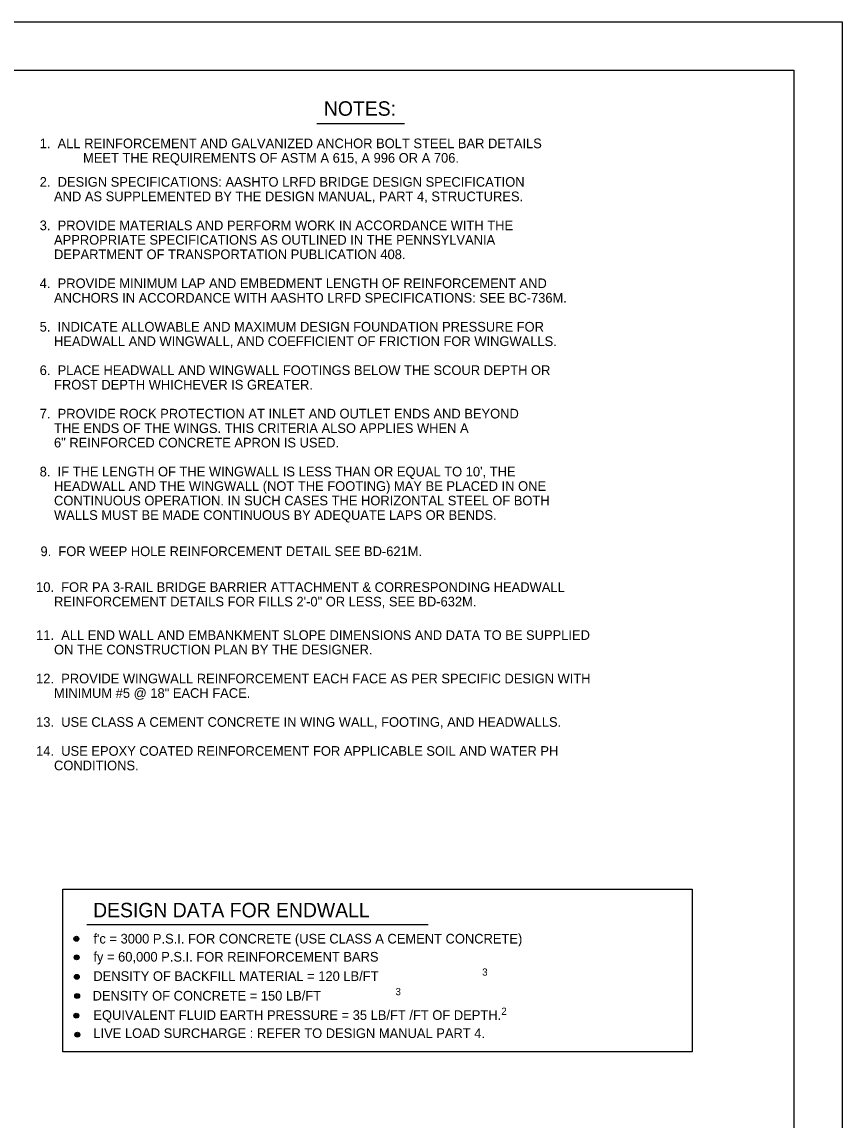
# Model space of a CAD drawing. Extents: x 639011 to 639866, y 298840 to 300028.
# Drawn here: x 639597.4 to 639852.3, y 299686.7 to 300027.8 of the extents above; entities that cross this region are included whole.
import ezdxf

# ---------------------------------------------------------------- set-up
doc = ezdxf.new("R2010")
doc.units = 0
doc.layers.add('2', color=7, linetype='Continuous')
doc.layers.add('PLT-BNDY', color=7, linetype='Continuous')

msp = doc.modelspace()

# ---------------------------------------------------------------- linework, layer by layer
at = {"layer": '2'}
for p, q in [((639051.26, 300012.83), (639837.26, 300012.83)), ((639837.26, 300012.83), (639837.26, 299448.83)), ((639689.02, 299996.32), (639716.27, 299996.32)), ((639617.6, 299747.4), (639723.63, 299747.4))]:
    msp.add_line(p, q, dxfattribs=at)
msp.add_lwpolyline([(639610.08, 299758.44), (639805.72, 299758.44), (639805.72, 299707.89), (639610.08, 299707.89)], close=True, dxfattribs=at)
for centre, radius in [((639614.32, 299743), 0.763), ((639614.32, 299743), 0.763), ((639614.32, 299743), 0.545), ((639614.32, 299743), 0.545), ((639614.32, 299743), 0.298), ((639614.32, 299743), 0.298), ((639614.32, 299743), 0.15), ((639614.32, 299743), 0.15), ((639614.32, 299743), 0.0644), ((639614.32, 299743), 0.0644), ((639614.4, 299737.23), 0.763), ((639614.4, 299737.23), 0.763), ((639614.4, 299737.23), 0.545), ((639614.4, 299737.23), 0.545), ((639614.4, 299737.23), 0.298), ((639614.4, 299737.23), 0.298), ((639614.4, 299737.23), 0.15), ((639614.4, 299737.23), 0.15), ((639614.4, 299737.23), 0.0644), ((639614.4, 299737.23), 0.0644), ((639614.46, 299731.16), 0.763), ((639614.46, 299731.16), 0.763), ((639614.46, 299731.16), 0.545), ((639614.46, 299731.16), 0.545), ((639614.46, 299731.16), 0.298), ((639614.46, 299731.16), 0.298), ((639614.46, 299731.16), 0.15), ((639614.46, 299731.16), 0.15), ((639614.46, 299731.16), 0.0644), ((639614.46, 299731.16), 0.0644), ((639614.56, 299725.2), 0.763), ((639614.56, 299725.2), 0.545), ((639614.56, 299725.2), 0.545), ((639614.56, 299725.2), 0.298), ((639614.56, 299725.2), 0.298), ((639614.56, 299725.2), 0.15), ((639614.56, 299725.2), 0.15), ((639614.56, 299725.2), 0.0644), ((639614.56, 299725.2), 0.0644), ((639614.3, 299719.1), 0.763), ((639614.3, 299719.1), 0.763), ((639614.3, 299719.1), 0.545), ((639614.3, 299719.1), 0.545), ((639614.3, 299719.1), 0.298), ((639614.3, 299719.1), 0.298), ((639614.3, 299719.1), 0.15), ((639614.3, 299719.1), 0.15), ((639614.3, 299719.1), 0.0644), ((639614.3, 299719.1), 0.0644), ((639614.62, 299713.18), 0.763), ((639614.62, 299713.18), 0.763), ((639614.62, 299713.18), 0.545), ((639614.62, 299713.18), 0.545), ((639614.62, 299713.18), 0.298), ((639614.62, 299713.18), 0.298), ((639614.62, 299713.18), 0.15), ((639614.62, 299713.18), 0.15), ((639614.62, 299713.18), 0.0644), ((639614.62, 299713.18), 0.0644)]:
    msp.add_circle(centre, radius, dxfattribs=at)
at = {"layer": 'PLT-BNDY'}
msp.add_lwpolyline([(639011.26, 300027.83), (639852.26, 300027.83), (639852.26, 299433.83), (639011.26, 299433.83)], close=True, dxfattribs=at)

# ---------------------------------------------------------------- texts
at = {"layer": '2'}
for s, height, p in [('NOTES:', 4.5, (639691.24, 299998.69)), (' 1.  ALL REINFORCEMENT AND GALVANIZED ANCHOR BOLT STEEL BAR DETAILS', 3, (639601.8, 299988.61)), ('MEET THE REQUIREMENTS OF ASTM A 615, A 996 OR A 706.', 3, (639616.4, 299984.11)), (' 2.  DESIGN SPECIFICATIONS: AASHTO LRFD BRIDGE DESIGN SPECIFICATION', 3, (639601.8, 299976.64)), ('     AND AS SUPPLEMENTED BY THE DESIGN MANUAL, PART 4, STRUCTURES.', 3, (639601.8, 299972.14)), (' 3.  PROVIDE MATERIALS AND PERFORM WORK IN ACCORDANCE WITH THE ', 3, (639601.8, 299963.14)), ('     APPROPRIATE SPECIFICATIONS AS OUTLINED IN THE PENNSYLVANIA', 3, (639601.8, 299958.64)), ('     DEPARTMENT OF TRANSPORTATION PUBLICATION 408.', 3, (639601.8, 299954.14)), (' 4.  PROVIDE MINIMUM LAP AND EMBEDMENT LENGTH OF REINFORCEMENT AND', 3, (639601.8, 299945.14)), ('     ANCHORS IN ACCORDANCE WITH AASHTO LRFD SPECIFICATIONS: SEE BC-736M.', 3, (639601.8, 299940.64)), (' 5.  INDICATE ALLOWABLE AND MAXIMUM DESIGN FOUNDATION PRESSURE FOR', 3, (639601.8, 299931.64)), ('     HEADWALL AND WINGWALL, AND COEFFICIENT OF FRICTION FOR WINGWALLS.', 3, (639601.8, 299927.14)), (' 6.  PLACE HEADWALL AND WINGWALL FOOTINGS BELOW THE SCOUR DEPTH OR ', 3, (639601.8, 299918.14)), ('     FROST DEPTH WHICHEVER IS GREATER.', 3, (639601.8, 299913.64)), (' 7.  PROVIDE ROCK PROTECTION AT INLET AND OUTLET ENDS AND BEYOND', 3, (639601.8, 299904.64)), ('     THE ENDS OF THE WINGS. THIS CRITERIA ALSO APPLIES WHEN A', 3, (639601.8, 299900.14)), ('     6" REINFORCED CONCRETE APRON IS USED.', 3, (639601.8, 299895.64)), (" 8.  IF THE LENGTH OF THE WINGWALL IS LESS THAN OR EQUAL TO 10', THE", 3, (639601.8, 299886.64)), ('     HEADWALL AND THE WINGWALL (NOT THE FOOTING) MAY BE PLACED IN ONE', 3, (639601.8, 299882.14)), ('     CONTINUOUS OPERATION. IN SUCH CASES THE HORIZONTAL STEEL OF BOTH', 3, (639601.8, 299877.64)), ('     WALLS MUST BE MADE CONTINUOUS BY ADEQUATE LAPS OR BENDS.', 3, (639601.8, 299873.14)), (' 9.  FOR WEEP HOLE REINFORCEMENT DETAIL SEE BD-621M.', 3, (639602.05, 299861.88)), ('10.  FOR PA 3-RAIL BRIDGE BARRIER ATTACHMENT & CORRESPONDING HEADWALL', 3, (639601.8, 299850.75)), ('     REINFORCEMENT DETAILS FOR FILLS 2\'-0" OR LESS, SEE BD-632M.', 3, (639601.8, 299846.25)), ('11.  ALL END WALL AND EMBANKMENT SLOPE DIMENSIONS AND DATA TO BE SUPPLIED', 3, (639601.8, 299835.84)), ('     ON THE CONSTRUCTION PLAN BY THE DESIGNER.', 3, (639601.8, 299831.34)), ('12.  PROVIDE WINGWALL REINFORCEMENT EACH FACE AS PER SPECIFIC DESIGN WITH', 3, (639601.8, 299822.34)), ('     MINIMUM #5 @ 18" EACH FACE.', 3, (639601.8, 299817.84)), ('13.  USE CLASS A CEMENT CONCRETE IN WING WALL, FOOTING, AND HEADWALLS.', 3, (639601.8, 299808.84)), ('14.  USE EPOXY COATED REINFORCEMENT FOR APPLICABLE SOIL AND WATER PH', 3, (639601.8, 299799.84)), ('     CONDITIONS.', 3, (639601.8, 299795.34)), ('DESIGN DATA FOR ENDWALL', 4.5, (639619.52, 299749.65)), ("f'c = 3000 P.S.I. FOR CONCRETE (USE CLASS A CEMENT CONCRETE)", 3, (639619.6, 299741.52)), ('fy = 60,000 P.S.I. FOR REINFORCEMENT BARS', 3, (639619.6, 299735.9)), ('3', 2.25, (639740.43, 299731.52)), ('DENSITY OF BACKFILL MATERIAL = 120 LB/FT', 3, (639619.6, 299729.9)), ('DENSITY OF CONCRETE = 150 LB/FT', 3, (639619.36, 299723.8)), ('3', 2.25, (639713.49, 299725.46)), ('EQUIVALENT FLUID EARTH PRESSURE = 35 LB/FT /FT OF DEPTH.', 3, (639619.6, 299717.79)), ('2', 2.25, (639746.38, 299719.35)), ('LIVE LOAD SURCHARGE : REFER TO DESIGN MANUAL PART 4.', 3, (639619.6, 299712.16))]:
    msp.add_text(s, height=height, dxfattribs=at).set_placement(p)

doc.saveas('drawing.dxf')
